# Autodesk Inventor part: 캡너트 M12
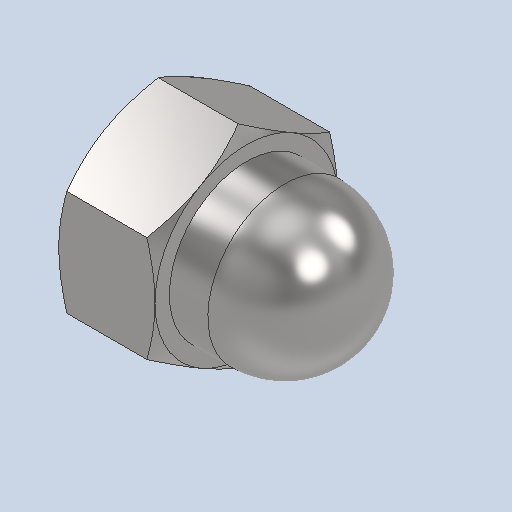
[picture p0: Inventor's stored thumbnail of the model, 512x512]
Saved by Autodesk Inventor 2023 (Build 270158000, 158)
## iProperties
Created: 2024-07
Part Number: 캡너트 M12
Material: 강철, 연강
Description: 6각 둥근캡 너트
Document SubType Name: Modeling
Designer: home
Density: 7.85 g/cm^3
Appearance: 기본값
Author: jhkim
Sending System: Autodesk Inventor 2025
Preprocessor: ST-DEVELOPER v20
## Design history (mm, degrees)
feature "Solid1"
node "솔리드1"
